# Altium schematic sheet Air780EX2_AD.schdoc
size 124 x 121 mm
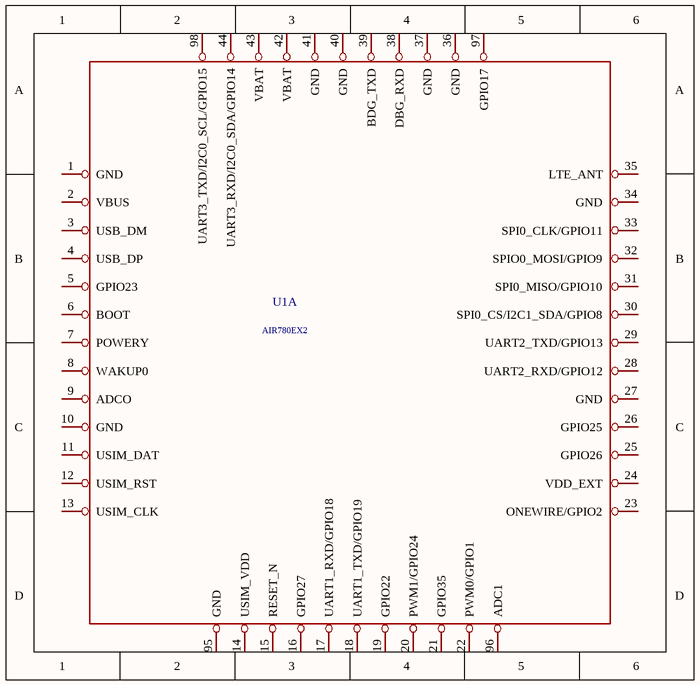
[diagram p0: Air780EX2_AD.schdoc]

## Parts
U1  AIR780EX2  (part A of 2)

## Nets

Not connected (* = marked no-connect by the designer): U1 1(GND) 2(VBUS) 3(USB_DM) 4(USB_DP) 5(GPIO23) 6(BOOT) 7(POWERY) 8(WAKUP0) 9(ADCO) 10(GND) 11(USIM_DAT) 12(USIM_RST) 13(USIM_CLK) 14(USIM_VDD) 15(RESET_N) 16(GPIO27) 17(UART1_RXD/GPIO18) 18(UART1_TXD/GPIO19) 19(GPIO22) 20(PWM1/GPIO24) 21(GPIO35) 22(PWM0/GPIO1) 23(ONEWIRE/GPIO2) 24(VDD_EXT) 25(GPIO26) 26(GPIO25) 27(GND) 28(UART2_RXD/GPIO12) 29(UART2_TXD/GPIO13) 30(SPI0_CS/I2C1_SDA/GPIO8) 31(SPI0_MISO/GPIO10) 32(SPIO0_MOSI/GPIO9) 33(SPI0_CLK/GPIO11) 34(GND) 35(LTE_ANT) 36(GND) 37(GND) 38(DBG_RXD) 39(BDG_TXD) 40(GND) 41(GND) 42(VBAT) 43(VBAT) 44(UART3_RXD/I2C0_SDA/GPIO14) 95(GND) 96(ADC1) 97(GPIO17) 98(UART3_TXD/I2C0_SCL/GPIO15)

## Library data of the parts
U1 = AIR780EX2: Add into BOM: yes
